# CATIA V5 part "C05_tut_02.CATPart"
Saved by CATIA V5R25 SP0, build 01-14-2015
Part number: Part1
Bounding box of the stored display mesh (mm): x -15 to 5, y -42.139 to 42.139, z 0 to 101.999
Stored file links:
  E:\ashutosh\Academics\Catia\CATIA V5-6R2013_partfiles\Tutorials_ver_2\C05_tut_02.CATPart
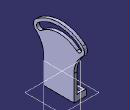
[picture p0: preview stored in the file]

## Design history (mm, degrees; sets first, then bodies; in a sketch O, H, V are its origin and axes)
Body1 (main body)
  Sketch1 on yz-plane, origin (0, 0, 0), H (0, 1, 0), V (0, 0, 1)
    point P1 (-25, 0)
    line L1 (-25, 0) -> (25, 0)
    point P2 (25, 0)
    line L2 (-25, 0) -> (-25, 42)
    point P3 (-25, 42)
    arc A1 centre (0, 42) radius 60 from (38.5673, 87.9627) to (-38.5673, 87.9627) ccw
    point P4 (0, 42)
    axis line L3 (0, 42) -> (-51.267, 103.0976)
    point P5 (-51.267, 103.0976)
    point P6 (51.267, 103.0976)
    point P7 (0, 42)
    construction line L4 (0, 42) -> (51.267, 103.0976)
    point P8 (-38.5673, 87.9627)
    point P9 (38.5673, 87.9627)
    arc A2 centre (-32.1394, 80.3022) radius 10 from (-38.5673, 87.9627) to (-38.8027, 72.8457) ccw
    point P10 (-32.1394, 80.3022)
    arc A3 centre (32.1394, 80.3022) radius 10 from (38.5673, 87.9627) to (38.8028, 72.8457) cw
    arc A4 centre (-66.3676, 42) radius 41.3676 from (-25, 42) to (-38.8027, 72.8457) ccw
    arc A5 centre (66.3676, 42) radius 41.3676 from (25, 42) to (38.8028, 72.8457) cw
    point P14 (25, 42)
    point P15 (25, 0)
    line L5 (25, 0) -> (25, 42)
    point P17 (25, 42)
    construction arc A6 centre (0, 42) radius 50 from (32.1394, 80.3022) to (-32.1394, 80.3022) ccw
    point P19 (-32.1394, 80.3022)
    arc A7 centre (32.1394, 80.3022) radius 5 from (35.3533, 84.1324) to (28.9255, 76.472) cw
    arc A8 centre (-32.1394, 80.3022) radius 5 from (-28.9254, 76.472) to (-35.3533, 84.1324) cw
    arc A9 centre (0, 42) radius 45 from (28.9255, 76.472) to (-28.9254, 76.472) ccw
    arc A10 centre (0, 42) radius 55 from (-35.3533, 84.1324) to (35.3533, 84.1324) cw
    length L1 = 50
    length L2 = 42
    radius A1 = 60
    angle L3 V = 40
    radius A2 = 10
    distance P4 L1 = 42
    radius A8 = 5
    coincidence: P1 H, P4 V, L3 P8, L4 P9, P10 L3, L5 P17, A6 P10, P19 L3, P2 P15, P14 P17
    horizontal: L1 H
    symmetry: P2 P1 V, P5 P6 V, P4 P7 V, L3 L4 V, A2 A3 V, A4 A5 V, P3 P14 V, P1 P15 V, L2 L5 V
    vertical: L2 V
    tangency: A2 A1, A4 A2, A4 L2, A5 A3, L5 A5, A9 A8, A8 A10, A10 A7, A7 A9
    concentricity: A9 P4, A10 P4
  Pad1: profile Sketch1, direction (1, 0, 0), length 5
  Sketch2 on yz-plane, origin (0, 0, 0), H (0, 1, 0), V (0, 0, 1)
    line L1 (-25, 10) -> (25, 10)
    line L2 (25, 10) -> (25, 0)
    line L3 (25, 0) -> (-25, 0)
    line L4 (-25, 0) -> (-25, 10)
    point P3 (25, 0)
    reference projected line E1 (25, 0) -> (25, 42) from edge [face of Pad1 from Sketch1.L5 | end face of Pad1]
    reference projected line E2 (-25, 42) -> (-25, 0) from edge [face of Pad1 from Sketch1.L2 | end face of Pad1]
    length L2 = 10
    horizontal: L1 H, L3 H
    vertical: L2 V, L4 V
    coincidence: P3 H, L2 E1, L4 E2
  Pad2: profile Sketch2, direction (-1, 0, 0), length 15
  Sketch3 on face of Pad2 from Sketch2.L1, origin (0, 0, 10), H (1, 0, 0), V (0, 1, 0)
    circle A1 centre (-9, 19) radius 2.5
    point P1 (-9, 19)
    reference projected line E1 (0, 25) -> (-15, 25) from edge [face of Pad2 | face of Pad2 from Sketch2.L1]
    reference projected line E2 (-15, 25) -> (-15, -25) from edge [end face of Pad2 | face of Pad2 from Sketch2.L1]
    circle A2 centre (-9, -19) radius 2.5
    radius A1 = 2.5
    distance E1 P1 = 6
    distance E2 P1 = 6
    symmetry: A1 A2 H
  Pocket1: profile Sketch3, direction (0, 0, -1), through (limit type 3)
  Sketch4 on start face of Pad1, origin (0, 0, 0), H (0, -1, 0), V (0, 0, 1)
    circle A1 centre (0, 40.6656) radius 11
    point P1 (0, 40.6656)
    circle A2 centre (0, 40.6656) radius 4
    radius A1 = 11
    radius A2 = 4
    coincidence: P1 V
  Pad3: profile Sketch4, direction (-1, 0, 0), length 9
